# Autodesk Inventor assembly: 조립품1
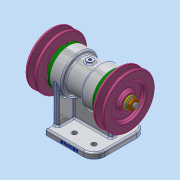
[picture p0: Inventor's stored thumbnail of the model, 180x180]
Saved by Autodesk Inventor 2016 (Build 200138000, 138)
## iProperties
Created: 2020-06
Part Number: 조립품1
Material: 일반
Document SubType Name: Assembly
Designer: 605-12
Author: 605-12
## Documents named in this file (12)
- C:\Users\605-12\Desktop\700606V1050\조립품1.iam
- C:\Users\605-12\Desktop\700606V1050\본체.ipt
- C:\Users\605-12\Desktop\700606V1050\베어링 6204.ipt
- C:\Users\605-12\Desktop\700606V1050\축.ipt
- C:\Users\605-12\Desktop\700606V1050\커버.ipt
- C:\Users\605-12\Desktop\700606V1050\볼트 M4.ipt
- C:\Users\605-12\Desktop\700606V1050\오일 실 20 32 5.ipt
- C:\Users\605-12\Desktop\700606V1050\키 5x5x12.ipt
- C:\Users\605-12\Desktop\700606V1050\V-벨트풀리.ipt
- C:\Users\605-12\Desktop\700606V1050\평면 와셔 10x21.ipt
- C:\Users\605-12\Desktop\700606V1050\스프링 와셔 10.ipt
- C:\Users\605-12\Desktop\700606V1050\너트 M10.ipt
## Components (2 placed, 1 different names)
1. V-벨트풀리:1
2. V-벨트풀리:2
